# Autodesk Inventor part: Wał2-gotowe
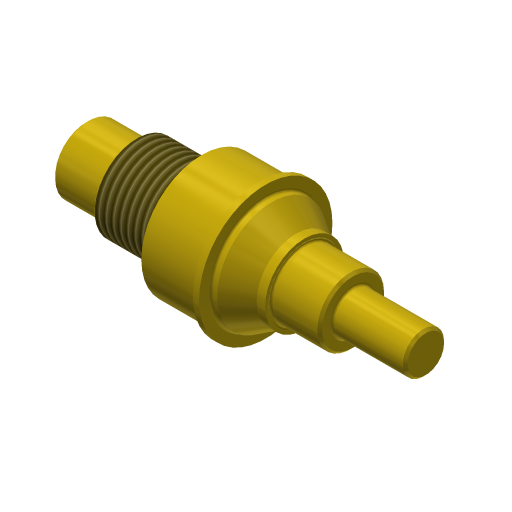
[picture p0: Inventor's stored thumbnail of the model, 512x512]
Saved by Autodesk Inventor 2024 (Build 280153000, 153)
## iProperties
Company: ATC
CustomPartVersion: 1
Created: 2023-03
Part Number: Wał2-gotowe
Material: Stal kuta
Document SubType Name: Modeling
Designer: Andrzej Jaskulski
Density: 1 g/cm^3
Stock Number: Wał2-gotowe
Appearance: Lśniąca — złota
Checked By: A.J.
Engr Approved By: Andrzej Jaskulski
Mfg Approved By: Andrzej Jaskulski
Authority: A.J.
Title: A.J.: Kurs R2024-MEP
Author: Andrzej Jaskulski
Revision Number: 1/24
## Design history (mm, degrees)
sketch "Szkic główny"
  geometry: L1 (0, 0)-(280, 0) reference; L2 (0, 0)-(0, 27.5); L3 (0, 27.5)-(40, 27.5); L4 (40, 27.5)-(40, 35); L5 (90, 35)-(90, 32.5); L6 (40, 35)-(90, 35); L7 (90, 32.5)-(95, 32.5); L8 (95, 32.5)-(95, 50); L9 (95, 50)-(143, 50); L10 (143, 50)-(143, 55); L11 (148, 55)-(148, 45); L12 (143, 55)-(148, 55); L13 (148, 45)-(153, 45); L14 (153, 45)-(173, 32.5); L15 (180, 32.5)-(180, 27.5); L16 (173, 32.5)-(180, 32.5); L17 (220, 27.5)-(220, 17); L18 (180, 27.5)-(220, 27.5); L19 (280, 17)-(280, 0); L20 (220, 17)-(280, 17)
  constraints: 40 end point, 9 vertical, 5 horizontal
  dimensions: "d14" = 70 diameter of L6 L1 (derived); "d15" = 65 diameter of L7 L1 (derived); "d16" = 110 diameter of L12 L1 (derived); "d17" = 90 diameter of L13 L1 (derived); "d18" = 65 diameter of L16 L1 (derived); "d19" = 34 diameter of L20 L1 (derived); "d45" = 55 diameter of L3 L1 (derived); "d46" = 100 diameter of L9 L1 (derived); "d47" = 55 diameter of L18 L1 (derived)
revolve "Obrót1" sketch "Szkic główny" stored, may be unused: angle "d6" = 0 deg
fillet "Zaokrąglenie7" dims "d48" = 2
chamfer "Faza3" distance "d20" = 2; stored, may be unused: second distance "d21" = 0.125, angle "d22" = 45 deg
chamfer "Faza4" distance "d24" = 2; stored, may be unused: second distance "d25" = 0.125, angle "d26" = 45 deg
node "Gwint2"
fillet "Zaokrąglenie8" dims "d49" = 0.5
node "Podcięcie3"
fillet "Zaokrąglenie3" dims "d32" = 0.5
chamfer "Faza6" distance "d34" = 0.5; stored, may be unused: second distance "d35" = 0.125, angle "d36" = 45 deg
fillet "Zaokrąglenie5" dims "d37" = 2
node "Podcięcie2"
chamfer "Faza7" distance "d38" = 2; stored, may be unused: second distance "d39" = 0.125, angle "d40" = 45 deg
fillet "Zaokrąglenie6" dims "d41" = 2
chamfer "Faza8" distance "d42" = 2; stored, may be unused: second distance "d43" = 0.125, angle "d44" = 45 deg
node "Bryła1"
node "Korpusy bryłowe"
node "Korpusy powierzchniowe"
feature "Gwint1" dims "d27" = 50, "d28" = 0
chamfer "Faza5" distance "d29" = 2; stored, may be unused: second distance "d30" = 2, angle "d31" = 45 deg
feature "iFeature1:2"
feature "iFeature1:3"
other parameters: "d0" = 0, "d1" = 0, "d2" = 0
